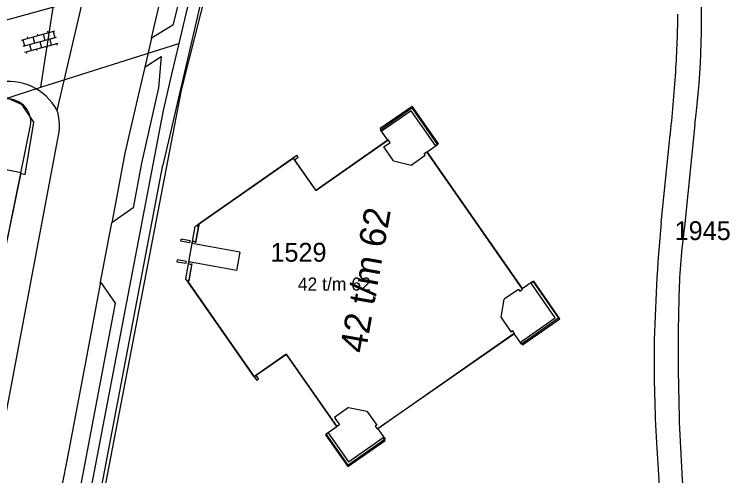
# Model space of a CAD drawing. Extents: x 148816 to 151297, y 399515 to 402500.
# Drawn here: x 149901.3 to 149969.6, y 400203.1 to 400247.2 of the extents above; entities that cross this region are included whole.
import ezdxf

# ---------------------------------------------------------------- set-up
doc = ezdxf.new("R2010")
doc.units = 0
for name, color, linetype in [('B01 Hoofdgebouw  [T] Norm', 7, 'Continuous'), ('B01 hoofgebouw', 7, 'Continuous'), ('G01 perceelsgrens', 7, 'Continuous'), ('G02 sectiegrens', 7, 'Continuous'), ('S02 Open verharding  Norm', 7, 'Continuous'), ('T01 Muur  [T] Gem', 7, 'Continuous'), ('V00 Kant verharding algemeen  [T] Norm', 7, 'Continuous'), ('V00 Kant verharding algemeen secundair  [T] Gem', 7, 'Continuous'), ('Z01 perceelnummer', 7, 'Continuous'), ('Z02 huisnummer', 7, 'Continuous'), ('Z02 Huisnummer  [Tekst] Norm', 7, 'Continuous')]:
    doc.layers.add(name, color=color, linetype=linetype)

msp = doc.modelspace()

# ---------------------------------------------------------------- linework, layer by layer
at = {"layer": 'B01 Hoofdgebouw  [T] Norm'}
for p, q in [((149937.154, 400234.941), (149936.971, 400235.203)), ((149936.547, 400234.517), (149937.154, 400234.941)), ((149937.492, 400233.164), (149936.547, 400234.517)), ((149901.95, 400232.02), (149893.76, 400233.69)), ((149928.388, 400233.537), (149928.268, 400233.709)), ((149939.154, 400232.763), (149940.507, 400233.708)), ((149940.398, 400233.864), (149940.652, 400234.041)), ((149940.507, 400233.708), (149940.398, 400233.864)), ((149928.027, 400233.285), (149928.388, 400233.537)), ((149930.058, 400230.376), (149928.027, 400233.285)), ((149937.492, 400233.164), (149939.154, 400232.763)), ((149899.1, 400218.26), (149901.95, 400232.02)), ((149917.943, 400221.728), (149917.868, 400221.676)), ((149949.414, 400220.898), (149948.051, 400219.963)), ((149949.414, 400220.898), (149949.52, 400220.753)), ((149947.739, 400218.221), (149948.685, 400216.865)), ((149948.685, 400216.865), (149948.832, 400216.969)), ((149927.251, 400214.72), (149924.343, 400212.703)), ((149924.343, 400212.703), (149924.594, 400212.341)), ((149924.594, 400212.341), (149924.421, 400212.221)), ((149933.19, 400209.625), (149931.837, 400208.681)), ((149933.19, 400209.625), (149934.945, 400209.296)), ((149934.945, 400209.296), (149935.888, 400207.942)), ((149931.837, 400208.681), (149932.323, 400207.984)), ((149932.323, 400207.984), (149932.069, 400207.807)), ((149935.888, 400207.942), (149935.74, 400207.839)), ((149935.74, 400207.839), (149935.917, 400207.585))]:
    msp.add_line(p, q, dxfattribs=at)
for points in [[(149930.058, 400230.376), (149936.971, 400235.203)], [(149918.852, 400227.145), (149928.268, 400233.709)], [(149949.52, 400220.753), (149949.771, 400220.937), (149940.652, 400234.041)], [(149918.839, 400227.13), (149918.897, 400227.053), (149918.588, 400225.353)], [(149918.294, 400225.505), (149918.257, 400225.302)], [(149917.946, 400223.529), (149917.906, 400223.326)], [(149918.241, 400223.368), (149917.943, 400221.728)], [(149917.868, 400221.676), (149924.421, 400212.221)], [(149947.739, 400218.221), (149948.051, 400219.963)], [(149935.917, 400207.585), (149949.014, 400216.713), (149948.832, 400216.969)], [(149927.251, 400214.72), (149932.069, 400207.807)]]:
    msp.add_lwpolyline(points, dxfattribs=at)
at = {"layer": 'B01 hoofgebouw'}
for points in [[(149927.904, 400233.424), (149930.051, 400230.344), (149936.926, 400235.139), (149936.23, 400236.14), (149939.22, 400238.226), (149941.684, 400234.694), (149940.681, 400233.999), (149949.762, 400220.979), (149950.762, 400221.679), (149953.224, 400218.148), (149949.693, 400215.685), (149948.993, 400216.685), (149935.976, 400207.606), (149936.677, 400206.607), (149933.146, 400204.143), (149931.061, 400207.133), (149932.061, 400207.831), (149927.264, 400214.709), (149924.185, 400212.561), (149917.806, 400221.707)], [(149894.2, 400219.27), (149899.1, 400218.26), (149901.95, 400232.02), (149893.76, 400233.69), (149892.96, 400229.83), (149890.91, 400230.26), (149889.88, 400225.36)], [(149917.806, 400221.707), (149917.978, 400221.826), (149918.233, 400223.257), (149917.909, 400223.315), (149918.298, 400225.5), (149918.623, 400225.442), (149918.878, 400226.873), (149918.758, 400227.045), (149927.904, 400233.424)], [(149918.878, 400226.873), (149918.758, 400227.045)]]:
    msp.add_lwpolyline(points, dxfattribs=at)
at = {"layer": 'G01 perceelsgrens'}
for points in [[(149928.683, 400290.07), (149928.133, 400287.86), (149924.892, 400275.537), (149920.7, 400258.889), (149917.834, 400247.891), (149916.98, 400244.39)], [(149929.124, 400286.945), (149917.218, 400239.933), (149906.317, 400183.184), (149904.793, 400174.189), (149903.698, 400165.135), (149903.033, 400156.039), (149902.799, 400146.923), (149903.023, 400135.058)], [(149903.825, 400240.198), (149905.472, 400250.942)], [(149936.926, 400235.139), (149936.23, 400236.14), (149939.22, 400238.226), (149941.684, 400234.694), (149940.681, 400233.999), (149949.762, 400220.979), (149950.762, 400221.679), (149953.224, 400218.148), (149949.693, 400215.685), (149948.993, 400216.685), (149935.976, 400207.606), (149936.677, 400206.607), (149933.146, 400204.143), (149931.061, 400207.133), (149932.061, 400207.831), (149927.264, 400214.709), (149924.185, 400212.561), (149917.66, 400221.917), (149918.546, 400226.897), (149927.904, 400233.424), (149930.051, 400230.344), (149936.926, 400235.139)], [(149900.51, 400225.11), (149901.92, 400231.99), (149902.85, 400236.54)]]:
    msp.add_lwpolyline(points, dxfattribs=at)
msp.add_arc((149900.64, 400236.854), 2.232, 351.91868, 101.63341, dxfattribs=at)
at = {"layer": 'G02 sectiegrens'}
for points in [[(149916.98, 400244.39), (149916.29, 400241.46), (149915.51, 400237.98), (149910.44, 400211.54), (149904.89, 400182.43), (149903.5, 400174.14), (149902.71, 400167.97), (149902.01, 400160.16), (149901.62, 400153.55), (149901.51, 400146.91), (149901.57, 400141.59), (149901.83, 400134.84), (149902.35, 400134.92)], [(149903.825, 400240.198), (149916.98, 400244.39)], [(149900.19, 400239.04), (149903.825, 400240.198)]]:
    msp.add_lwpolyline(points, dxfattribs=at)
at = {"layer": 'S02 Open verharding  Norm'}
for p, q in [((149901.968, 400244.692), (149905.149, 400245.572)), ((149904.522, 400245.399), (149904.482, 400245.544)), ((149905.004, 400245.532), (149905.164, 400244.954)), ((149902.113, 400244.732), (149902.273, 400244.154)), ((149902.129, 400244.114), (149905.309, 400244.994)), ((149902.595, 400244.865), (149902.555, 400245.01)), ((149903.077, 400244.999), (149903.237, 400244.421)), ((149903.559, 400245.132), (149903.519, 400245.277)), ((149904.041, 400245.266), (149904.201, 400244.687)), ((149904.843, 400244.242), (149904.683, 400244.821)), ((149902.289, 400243.536), (149905.469, 400244.416)), ((149902.755, 400244.287), (149902.915, 400243.709)), ((149903.719, 400244.554), (149903.879, 400243.976)), ((149904.361, 400244.109), (149904.401, 400243.965)), ((149905.324, 400244.376), (149905.364, 400244.231)), ((149902.433, 400243.576), (149902.473, 400243.431)), ((149903.397, 400243.842), (149903.437, 400243.698))]:
    msp.add_line(p, q, dxfattribs=at)
at = {"layer": 'T01 Muur  [T] Gem'}
for p, q in [((149939.165, 400237.956), (149936.409, 400236.026)), ((149941.494, 400234.631), (149939.165, 400237.956)), ((149941.757, 400234.815), (149939.243, 400238.405)), ((149941.757, 400234.815), (149941.494, 400234.631)), ((149917.179, 400225.498), (149917.21, 400225.696)), ((149918.027, 400225.35), (149917.179, 400225.498)), ((149918.061, 400225.547), (149917.213, 400225.695)), ((149918.061, 400225.547), (149918.027, 400225.35)), ((149918.605, 400225.448), (149918.294, 400225.505)), ((149922.822, 400224.472), (149918.257, 400225.302)), ((149922.822, 400224.472), (149922.511, 400222.699)), ((149916.833, 400223.519), (149916.865, 400223.717)), ((149917.672, 400223.369), (149916.833, 400223.519)), ((149917.707, 400223.566), (149916.868, 400223.716)), ((149917.707, 400223.566), (149917.672, 400223.369)), ((149922.511, 400222.699), (149917.946, 400223.529)), ((149918.223, 400223.268), (149917.906, 400223.326)), ((149950.867, 400221.687), (149950.604, 400221.505)), ((149949.593, 400215.882), (149949.776, 400215.62)), ((149931.251, 400207.222), (149930.991, 400207.042)), ((149931.25, 400207.223), (149933.183, 400204.455)), ((149930.991, 400207.042), (149933.107, 400204.012)), ((149933.107, 400204.012), (149936.672, 400206.495)), ((149933.183, 400204.455), (149936.489, 400206.757)), ((149936.672, 400206.495), (149936.486, 400206.755))]:
    msp.add_line(p, q, dxfattribs=at)
for points in [[(149936.409, 400236.026), (149936.22, 400236.288), (149939.243, 400238.405)], [(149949.593, 400215.882), (149952.901, 400218.189), (149950.604, 400221.505)], [(149949.776, 400215.62), (149953.346, 400218.109), (149950.867, 400221.687)]]:
    msp.add_lwpolyline(points, dxfattribs=at)
at = {"layer": 'V00 Kant verharding algemeen  [T] Norm'}
for p, q in [((149919.45, 400249.984), (149915.478, 400232.762)), ((149914.39, 400244.892), (149913.749, 400242.127)), ((149896.267, 400186.638), (149905.455, 400235.27)), ((149906.836, 400187.309), (149915.478, 400232.762)), ((149901.938, 400231.961), (149902.333, 400231.879)), ((149909.503, 400221.435), (149910.596, 400227.253)), ((149909.503, 400221.435), (149908.21, 400214.643)), ((149908.21, 400214.643), (149906.489, 400205.552)), ((149906.489, 400205.552), (149904.293, 400194.4))]:
    msp.add_line(p, q, dxfattribs=at)
for points in [[(149919.785, 400266.737), (149921.022, 400264.443), (149916.423, 400246.131), (149914.39, 400244.892)], [(149914.39, 400244.892), (149915.916, 400251.453), (149917.694, 400258.48), (149919.473, 400265.506), (149919.785, 400266.737)], [(149858.411, 400235.024), (149905.21, 400247.898)], [(149913.749, 400242.127), (149915.313, 400243.133), (149915.064, 400240.139), (149913.433, 400232.949), (149912.624, 400228.682), (149910.613, 400227.265)], [(149913.749, 400242.127), (149913.119, 400239.406), (149911.848, 400233.92), (149910.613, 400227.265)], [(149902.333, 400231.879), (149903.174, 400236.854), (149902.038, 400238.513), (149900.484, 400239.238), (149900.484, 400239.238)], [(149966.241, 400236.648), (149965.248, 400226.883)], [(149963.004, 400227.265), (149963.807, 400235.029)], [(149909.547, 400221.557), (149910.904, 400219.596), (149904.299, 400184.706), (149902.328, 400183.332)]]:
    msp.add_lwpolyline(points, dxfattribs=at)
for centre, radius, start, end in [((149887.565, 400246.628), 79.306, 352.77066, 4.06439), ((149855.287, 400248.521), 109.337, 356.20762, 359.28906), ((149840.207, 400249.578), 124.453, 353.28654, 356.18103), ((149900.724, 400235.479), 5.288, 28.29463, 101.68911), ((149900.282, 400236.488), 5.315, 346.75056, 16.37083), ((150134.181, 400211.828), 171.872, 174.84707, 178.81729), ((150022.633, 400218.857), 57.944, 172.03768, 178.47162), ((150173.843, 400214.988), 209.203, 178.51698, 181.85027), ((150095.12, 400214.151), 132.779, 179.47124, 183.39956), ((150103.322, 400212.655), 138.643, 181.82776, 185.86823), ((150122.081, 400213.864), 159.687, 182.72326, 185.65203)]:
    msp.add_arc(centre, radius, start, end, dxfattribs=at)
at = {"layer": 'V00 Kant verharding algemeen secundair  [T] Gem'}
msp.add_lwpolyline([(149905.381, 400237.986), (149908.196, 400250.021)], dxfattribs=at)

# ---------------------------------------------------------------- texts
at = {"layer": 'Z01 perceelnummer'}
for s, p in [('1945', (149964.301, 400225.611)), ('1529', (149925.732, 400223.549))]:
    msp.add_text(s, height=1.8, dxfattribs=at).set_placement(p)
at = {"layer": 'Z02 huisnummer'}
msp.add_text('42 t/m 62', height=2.5, rotation=79.92567, dxfattribs=at).set_placement((149934.799, 400214.732))
at = {"layer": 'Z02 Huisnummer  [Tekst] Norm'}
msp.add_text('42 t/m 62', height=1.25, dxfattribs=at).set_placement((149928.344, 400220.79))

doc.saveas('drawing.dxf')
